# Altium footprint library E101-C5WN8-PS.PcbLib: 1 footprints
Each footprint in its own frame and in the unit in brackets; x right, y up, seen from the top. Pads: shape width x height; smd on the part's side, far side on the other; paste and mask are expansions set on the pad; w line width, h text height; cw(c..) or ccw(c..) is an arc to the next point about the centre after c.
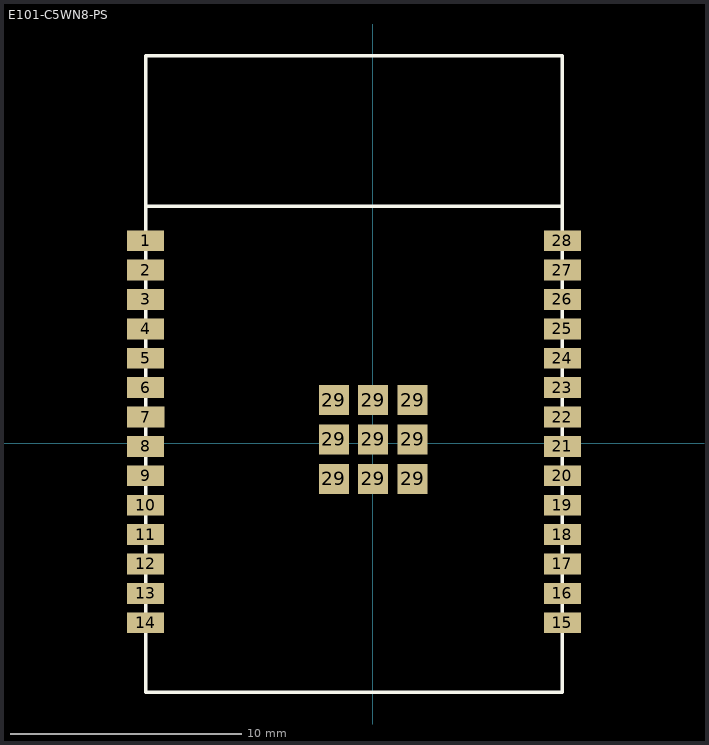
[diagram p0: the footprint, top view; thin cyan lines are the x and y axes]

## E101-C5WN8-PS [mm]
pads (37):
  rect 1.6x0.9 smd: 1(-9.82,8.75) 2(-9.82,7.48) 3(-9.82,6.21) 4(-9.82,4.94) 5(-9.82,3.67) 6(-9.82,2.4) 7(-9.82,1.13) 8(-9.82,-0.14) 9(-9.82,-1.41) 10(-9.82,-2.68) 11(-9.82,-3.95) 12(-9.82,-5.22) 13(-9.82,-6.49) 14(-9.82,-7.76) 15(8.18,-7.76) 16(8.18,-6.49) 17(8.18,-5.22) 18(8.18,-3.95) 19(8.18,-2.68) 20(8.18,-1.41) 21(8.18,-0.14) 22(8.18,1.13) 23(8.18,2.4) 24(8.18,3.67) 25(8.18,4.94) 26(8.18,6.21) 27(8.18,7.48) 28(8.18,8.75)
  rect 1.3x1.3 smd: 29(-1.69,-1.54) 29(-1.69,0.16) 29(-1.69,1.86) 29(0.01,-1.54) 29(0.01,0.16) 29(0.01,1.86) 29(1.71,-1.54) 29(1.71,0.16) 29(1.71,1.86)
Top Overlay:
  lines w0.15: -9.82,10.24 8.18,10.24 ; -9.82,-10.76 8.18,-10.76 8.18,16.74 -9.82,16.74 -9.82,-10.76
